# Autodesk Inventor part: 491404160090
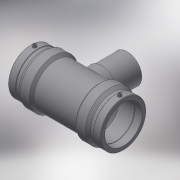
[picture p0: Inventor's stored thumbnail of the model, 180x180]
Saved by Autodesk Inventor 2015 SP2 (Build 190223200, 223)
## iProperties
Created: 2017-06
Part Number: 491404160090
Material: Generic
Description: PLASSON REDUCING TEE 160x90x160
Document SubType Name: Modeling
Designer: KIM
Mass: 4737.67 g
Surface Area: 5136.24 cm^2
Volume: 4737.67 cm^3
Density: 1 g/cm^3
Appearance: Default
Author: KIM
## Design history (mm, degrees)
derived "491404.ipt"
feature "Solid1::491404.ipt"
tag "TaggingFeature1"
body "Solid1"
other parameters: "d0" = 396, "d2" = 209, "d3" = 97, "d4" = 79.2, "d5" = 188.1, "d6" = 152, "d8" = 168 deg, "d10" = 38.8, "d11" = 12.93333, "d13" = 396, "d14" = 17.6296, "d17" = 144, "d19" = 3.52592, "d20" = 168 deg, "d22" = 194.37, "d23" = 209, "d25" = 135 deg, "d26" = 277.2, "d29" = 105, "d30" = 15, "d31" = 158.4, "d34" = 5 deg, "d35" = 15, "d39" = 5 deg, "d41" = 4, "d42" = 14, "d43" = 0, "d45" = 4, "d46" = 6, "d47" = 0, "d48" = -192, "d51" = 0, "d52" = 72, "d54" = 0, "d55" = 188.1, "d56" = 209, "d57" = 138.6, "d58" = 135 deg, "d59" = 97, "d60" = 97, "d61" = 135 deg, "d62" = 192, "d72" = 180.18, "d73" = 90.09, "d74" = -192, "d75" = 94.5, "d77" = 0, "d78" = 72, "d80" = 0, "d82" = 87.5, "d83" = 0, "d84" = 3, "d85" = 0, "d86" = 32.33333, "d87" = 190.4826, "d88" = 12.93333, "d89" = 3, "d90" = 0, "L_" = 396, "L_1" = 97, "D_" = 209, "A_" = 105, "d_2" = 12, "H_" = 192
